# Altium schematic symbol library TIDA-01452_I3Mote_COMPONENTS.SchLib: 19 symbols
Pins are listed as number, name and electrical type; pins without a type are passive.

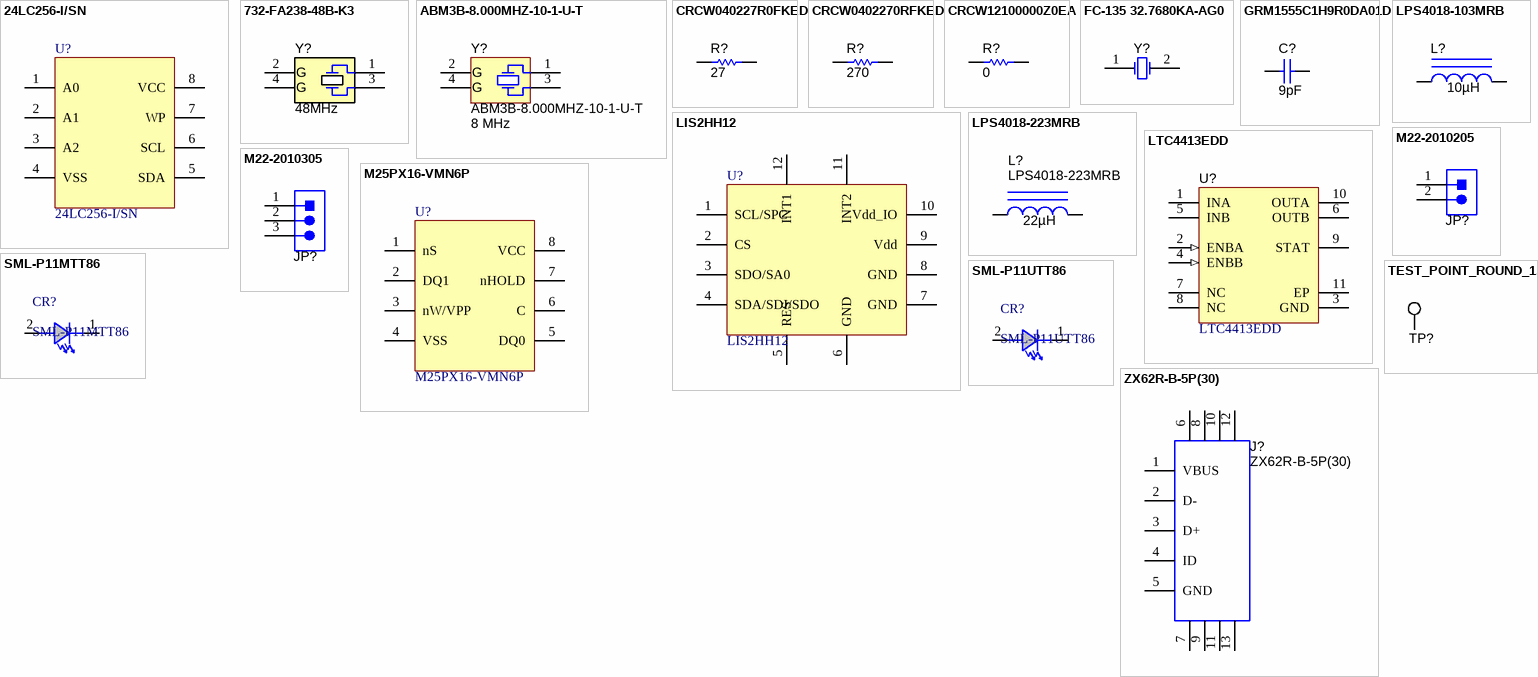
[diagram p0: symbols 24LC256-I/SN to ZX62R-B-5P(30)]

## 24LC256-I/SN
designator U?
256K I2C CMOS Serial EEPROM; Manufacturer: Microchip
footprint D0008A_N (SOIC, 8-Leads, Body 4.9x3.9mm, Pitch 1.27mm, IPC Medium Density)
pins: 1 A0, 2 A1, 3 A2, 4 VSS, 5 SDA, 6 SCL, 7 WP, 8 VCC

## 732-FA238-48B-K3
designator Y?  Frequency: 48MHz  (hidden comment: 732-FA238-48B-K3)
Crystal, 48MHz, 10pF, SMD; Manufacturer: Epson
footprint HEC_X3S048000BG1H-U
pins: 1, 2 GND (power), 3, 4 GND (power)

## ABM3B-8.000MHZ-10-1-U-T
designator Y?  Frequency: 8 MHz
Crystal, 8 MHz, 18 pF, SMD; Manufacturer: Abracon
footprint XTL14S (Footprint not found)
pins: 1, 2 GND (power), 3, 4 GND (power)

## CRCW040227R0FKED
designator R?  ValueDisplayed: 27  (hidden comment: CRCW040227R0FKED)
RES, 27, 1%, 0.25 W, 0402; Manufacturer: Vishay-Dale; Value: 27
signal-integrity model Resistor
simulation model Resistor
footprint 0402 (0402 from SM-752 data)
pins: 1, 2

## CRCW0402270RFKED
designator R?  ValueDisplayed: 270  (hidden comment: CRCW0402270RFKED)
RES, 270, 1%, 0.0625W, 50V, 0402; Manufacturer: Vishay-Dale; Value: 270
signal-integrity model Resistor
simulation model Resistor
footprint 0402 (0402 from SM-752 data)
pins: 1, 2

## CRCW12100000Z0EA
designator R?  ValueDisplayed: 0  (hidden comment: CRCW12100000Z0EA)
RES, 0, 0.5 W, 1210; Manufacturer: Vishay-Dale; Value: 0
footprint RESC3225X60N (Resistor, Chip;3.20 mm L X 2.50 mm W X 0.60 mm H body)
pins: 1, 2

## FC-135 32.7680KA-AG0
designator Y?  (value not drawn)
Crystal, 32.768 KHz, 7 pF, SMD; Manufacturer: Epson; U/M: EA; TaMin_C: -40; TaMax_C: 85; Frequency Tolerance: ±20ppm
footprint Epson_FC-135
pins: 1 OSC1, 2 OSC2

## GRM1555C1H9R0DA01D
designator C?  ValueDisplayed: 9pF  (hidden comment: GRM1555C1H9R0DA01D)
CAP, CERM, 9pF, 50V, +/- 0.5pF, C0G/NP0, 0402; Manufacturer: MuRata; CompType: Capacitor; VDC_V: 50; Cap_Case: 0402
signal-integrity model Cap
simulation model Cap
footprint 0402
footprint 0402M
footprint 0402L
footprint 0402S
pins: 1, 2

## LIS2HH12
designator U?
Ultra-low-power high-performance 3-axis pico accelerometer; Manufacturer: ST Microelectronics
footprint LGA12-2X2MM_0_50 (LGA, 12-Leads, Body 2x2mm, Pitch 0.5mm)
pins: 1 SCL/SPC, 2 CS, 3 SDO/SA0, 4 SDA/SDI/SDO, 5 RES, 6 GND, 7 GND, 8 GND, 9 Vdd, 10 Vdd_IO, 11 INT2, 12 INT1

## LPS4018-103MRB
designator L?  ValueDisplayed: 10µH  (hidden comment: LPS4018-103MRB)
Inductor, Shielded Drum Core, Ferrite, 10 µH, 1.25 A, 0.2 ohm, SMD; Manufacturer: Coilcraft; Value: 10uH; Value1: 0.2 ohm; Value2: 1.25A
signal-integrity model Inductor
simulation model Inductor
footprint LPS4018
pins: 1, 2

## LPS4018-223MRB
designator L?  ValueDisplayed: 22µH
Inductor, Shielded Drum Core, Ferrite, 22 µH, 0.83 A, 0.36 ohm, SMD; Manufacturer: Coilcraft; Value: 22uH
signal-integrity model Inductor
simulation model Inductor
footprint LPS4018
pins: 1, 2

## LTC4413EDD
designator U?
Dual 2.6 A, Ideal Diode, 2.5 to 5.5 V Vin, 10-pin SON (DD-10), -40 to 85 degC; Manufacturer: Linear Technology; Ideal Diode: Dual, Internal, P-Channel
footprint LT-DD-10_V (SON, 10-Leads, Body 3x3mm, Pitch 0.5mm, Thermal Pad 2.38x1.65mm)
pins: 1 INA (power), 2 ENBA (in), 3 GND (power), 4 ENBB (in), 5 INB (power), 6 OUTB (power), 7 NC "No Connection.", 8 NC "No Connection.", 9 STAT (oc), 10 OUTA (power), 11 EP (power)

## M22-2010205
designator JP?  (value not drawn)
Header, 2mm, 2x1, Tin, TH; Manufacturer: Harwin
footprint CONN_TMM-102-01-T-S
pins: 1, 2
1 alternate drawing of the same symbol

## M22-2010305
designator JP?  (value not drawn)
Header, 2mm, 3x1, Tin, TH; Manufacturer: Harwin
footprint CONN_TMM-103-01-T-S
pins: 1, 2, 3
3 alternate drawings of the same symbol

## M25PX16-VMN6P
designator U?
16Mbit Serial Flash Memory, SPI bus inferface; Manufacturer: Micron
footprint D0008A_N (SOIC, 8-Leads, Body 4.9x3.9mm, Pitch 1.27mm, IPC Medium Density)
pins: 1 nS, 2 DQ1, 3 nW/VPP, 4 VSS, 5 DQ0, 6 C, 7 nHOLD, 8 VCC

## SML-P11MTT86
designator CR?
Green 569nm LED Indication - Discrete 1.9V 0402 (1005 Metric); Manufacturer: Rohm Semiconductor; PCB Package: 0402
footprint LEDC1707X65L
pins: 1 C, 2 A

## SML-P11UTT86
designator CR?
Red 621nm LED Indication - Discrete 1.8V 0402 (1005 Metric); Manufacturer: Rohm Semiconductor; PCB Package: 0402
footprint LEDC1708X67L
pins: 1 C, 2 A

## TEST_POINT_ROUND_1.2
designator TP?, comment NA  (value not drawn)
Round Test Point, 1.2mm diam.
footprint Keystone5000
footprint TPS1.2
pins: 1

## ZX62R-B-5P(30)
designator J?
Connector, Receptacle, Micro-USB Type B, SMT; Manufacturer: Hirose Electric Co. Ltd.
footprint Hirose_ZX62R-B-5P
pins: 1 VBUS, 2 D-, 3 D+, 4 ID, 5 GND, 6, 7, 8, 9, 10, 11, 12, 13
